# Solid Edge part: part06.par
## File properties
Author: Robert a Rhodes jr
Template: normal.par
Last saved by: CADCIM
Revision: 10
Application: Solid Edge
Accuracy: 0.99
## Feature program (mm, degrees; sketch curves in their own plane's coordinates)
sketch for "unnamed Protrusion 1" plane through (0, 0, 0) normal (0, -1, 0) x-axis (1, 0, 0)
  arc centre (60, 0) radius 30 from (60, 30) to (60, -30) cw
  line (104, -30) -> (60, -30)
  line (104, 18) -> (104, -30)
  line (164, 18) -> (104, 18)
  line (164, -4) -> (164, 18)
  line (182, -4) -> (164, -4)
  line (182, -4) -> (182, 36)
  line (142, 36) -> (182, 36)
  line (142, 30) -> (142, 36)
  line (60, 30) -> (142, 30)
extrude "unnamed Protrusion 1" add finite 54 symmetric
sketch for "ExtrudedProtrusion_6" #1 plane through (0, 0, 0) normal (0, -1, 0) x-axis (1, 0, 0)
  arc centre (60, 0) radius 30 from (60, 30) to (60, -30) ccw
  arc centre (60, 0) radius 30 from (60, 30) to (60, -30) cw
sketch for "ExtrudedProtrusion_6" #2 plane through (0, 0, 0) normal (0, -1, 0) x-axis (1, 0, 0)
  circle centre (60, 0) radius 18
extrude "ExtrudedProtrusion_6" add finite 66 symmetric
sketch for "ExtrudedProtrusion_7" plane through (0, 0, 0) normal (0, -1, 0) x-axis (1, 0, 0)
  line (104, -30) -> (164, -4)
  line (164, -4) -> (164, 18)
  line (164, 18) -> (104, 18)
  line (104, 18) -> (104, -30)
extrude "ExtrudedProtrusion_7" add finite 18 symmetric
sketch for "ExtrudedProtrusion_8" plane through (0, 0, 0) normal (0, -1, 0) x-axis (1, 0, 0)
  line (200, 76) -> (200, -4)
  line (200, -4) -> (182, -4)
  line (182, -4) -> (182, 36)
  line (182, 76) -> (182, 36)
  line (182, 76) -> (200, 76)
extrude "ExtrudedProtrusion_8" add finite 92 symmetric
sketch for "ExtrudedProtrusion_9" plane through (0, 0, 0) normal (0, -1, 0) x-axis (1, 0, 0)
  line (142, 36) -> (182, 76)
  line (182, 76) -> (182, 36)
  line (142, 36) -> (182, 36)
extrude "ExtrudedProtrusion_9" add finite 12 symmetric
sketch for "unnamed Hole 1" plane through (200, 0, 36) normal (1, 0, 0) x-axis (0, 1, 0)
hole "unnamed Hole 1" through
sketch for "Hole_1" plane through (200, 0, 36) normal (1, 0, 0) x-axis (0, 1, 0)
  hole centre (-30, 22) bore radius 8
hole "Hole_1" diameter 16 through
pattern "unnamed Pattern 1" of "unnamed Hole 1", "Hole_1"
fillet "unnamed Round 1"
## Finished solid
Body 1: solid body, 34 faces, 81 edges, 46 vertices.
  Faces by surface: plane 28, cylinder 6
  Edges by curve: line 67, circle 14
Bounding box of the edges (mm): 170.000 x 92.000 x 106.000, from (30, -46, -30) to (200, 46, 76).
Cylindrical faces by radius (mm): R8 x2, R16 x2, R18 x1, R30 x1
Planar faces by outward normal: +x 3, +y 5, +z 4, -x 5, -y 5, -z 4, oblique 2
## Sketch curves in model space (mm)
circle centre (60, 0, 0) radius 18
line (182, 0, -4) -> (164, 0, -4)
line (104, 0, -30) -> (60, 0, -30)
arc centre (60, 0, 0) radius 30 from (60, 0, 30) through (30.0132, 0, -0.889) to (60, 0, -30)
arc centre (60, 0, 0) radius 30 from (60, 0, 30) through (89.9868, 0, -0.889) to (60, 0, -30)
line (142, 0, 36) -> (182, 0, 76)
line (142, 0, 36) -> (182, 0, 36)
line (104, 0, -30) -> (164, 0, -4)
line (182, 0, 76) -> (182, 0, 36)
line (182, 0, -4) -> (182, 0, 36)
line (142, 0, 30) -> (142, 0, 36)
line (60, 0, 30) -> (142, 0, 30)
line (104, 0, 18) -> (104, 0, -30)
line (164, 0, 18) -> (104, 0, 18)
line (164, 0, -4) -> (164, 0, 18)
line (200, 0, -4) -> (182, 0, -4)
line (200, 0, 76) -> (200, 0, -4)
line (182, 0, 76) -> (200, 0, 76)
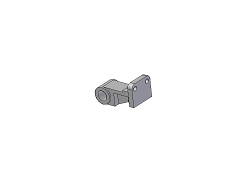
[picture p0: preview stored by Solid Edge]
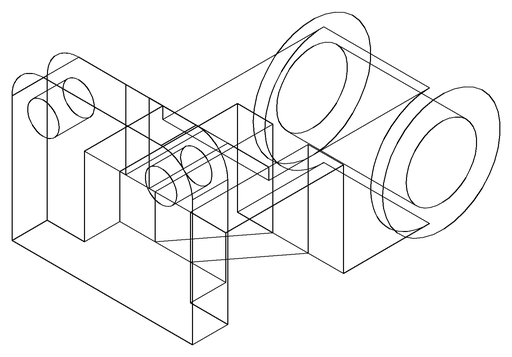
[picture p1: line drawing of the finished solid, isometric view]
